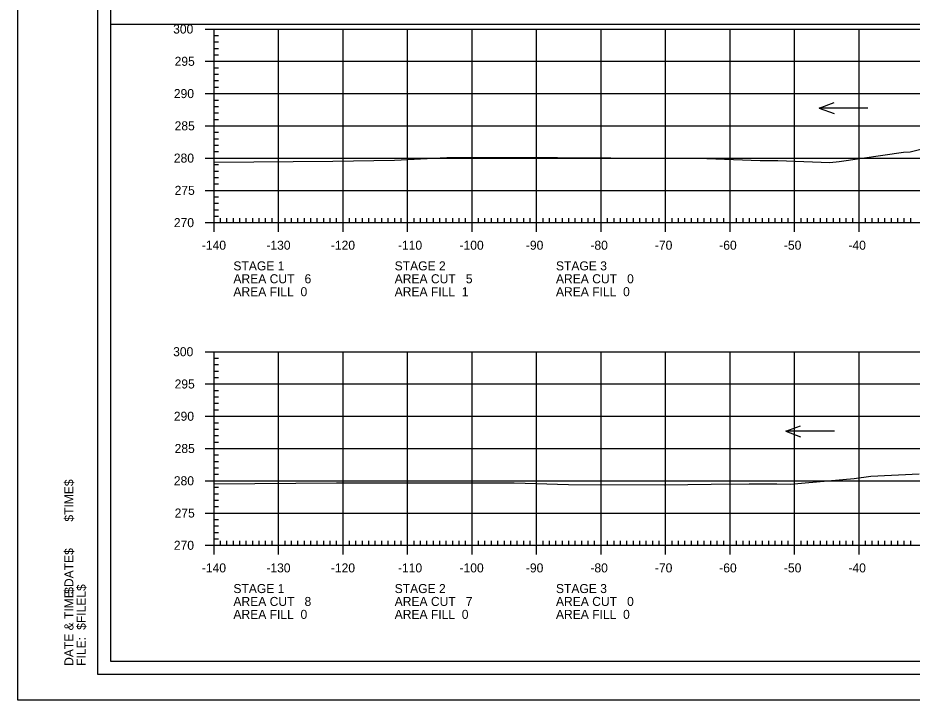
# Model space of a CAD drawing. Extents: x 1368713 to 1370673, y 380279 to 380950.
# Drawn here: x 1370339.2 to 1370477.8, y 380310.4 to 380416.1 of the extents above; entities that cross this region are included whole.
import ezdxf

# ---------------------------------------------------------------- set-up
doc = ezdxf.new("R2010")
doc.units = 0
for name, color, linetype in [('R_Axis', 7, 'Continuous'), ('R_Axis Annot', 7, 'Continuous'), ('R_Border', 7, 'Continuous'), ('R_Border Notes', 7, 'Continuous'), ('R_Exist Surface', 7, 'Continuous'), ('R_Grid', 7, 'Continuous'), ('R_No Plot', 7, 'Continuous'), ('R_Water Annot', 7, 'Continuous')]:
    doc.layers.add(name, color=color, linetype=linetype)

msp = doc.modelspace()

# ---------------------------------------------------------------- linework, layer by layer
at = {"layer": 'R_Axis'}
for p, q in [((1370368.23, 380414.42), (1370371.03, 380414.42)), ((1370369.63, 380384.42), (1370369.63, 380414.42)), ((1370369.63, 380413.42), (1370370.33, 380413.42)), ((1370369.63, 380412.42), (1370370.33, 380412.42)), ((1370369.63, 380411.42), (1370370.33, 380411.42)), ((1370369.63, 380410.42), (1370370.33, 380410.42)), ((1370368.23, 380409.42), (1370371.03, 380409.42)), ((1370369.63, 380408.42), (1370370.33, 380408.42)), ((1370369.63, 380407.42), (1370370.33, 380407.42)), ((1370369.63, 380406.42), (1370370.33, 380406.42)), ((1370369.63, 380405.42), (1370370.33, 380405.42)), ((1370368.23, 380404.42), (1370371.03, 380404.42)), ((1370369.63, 380403.42), (1370370.33, 380403.42)), ((1370369.63, 380402.42), (1370370.33, 380402.42)), ((1370369.63, 380401.42), (1370370.33, 380401.42)), ((1370369.63, 380400.42), (1370370.33, 380400.42)), ((1370368.23, 380399.42), (1370371.03, 380399.42)), ((1370369.63, 380398.42), (1370370.33, 380398.42)), ((1370369.63, 380397.42), (1370370.33, 380397.42)), ((1370369.63, 380396.42), (1370370.33, 380396.42)), ((1370368.23, 380394.42), (1370371.03, 380394.42)), ((1370369.63, 380395.42), (1370370.33, 380395.42)), ((1370369.63, 380393.42), (1370370.33, 380393.42)), ((1370369.63, 380392.42), (1370370.33, 380392.42)), ((1370369.63, 380391.42), (1370370.33, 380391.42)), ((1370369.63, 380390.42), (1370370.33, 380390.42)), ((1370368.23, 380389.42), (1370371.03, 380389.42)), ((1370369.63, 380388.42), (1370370.33, 380388.42)), ((1370369.63, 380387.42), (1370370.33, 380387.42)), ((1370369.63, 380386.42), (1370370.33, 380386.42)), ((1370369.63, 380383.02), (1370369.63, 380385.82)), ((1370369.63, 380385.42), (1370370.33, 380385.42)), ((1370370.63, 380384.42), (1370370.63, 380385.12)), ((1370371.63, 380384.42), (1370371.63, 380385.12)), ((1370372.63, 380384.42), (1370372.63, 380385.12)), ((1370373.63, 380384.42), (1370373.63, 380385.12)), ((1370374.63, 380384.42), (1370374.63, 380385.12)), ((1370375.63, 380384.42), (1370375.63, 380385.12)), ((1370376.63, 380384.42), (1370376.63, 380385.12)), ((1370377.63, 380384.42), (1370377.63, 380385.12)), ((1370378.63, 380384.42), (1370378.63, 380385.12)), ((1370379.63, 380383.02), (1370379.63, 380385.82)), ((1370380.63, 380384.42), (1370380.63, 380385.12)), ((1370381.63, 380384.42), (1370381.63, 380385.12)), ((1370382.63, 380384.42), (1370382.63, 380385.12)), ((1370383.63, 380384.42), (1370383.63, 380385.12)), ((1370384.63, 380384.42), (1370384.63, 380385.12)), ((1370385.63, 380384.42), (1370385.63, 380385.12)), ((1370386.63, 380384.42), (1370386.63, 380385.12)), ((1370387.63, 380384.42), (1370387.63, 380385.12)), ((1370388.63, 380384.42), (1370388.63, 380385.12)), ((1370389.63, 380383.02), (1370389.63, 380385.82)), ((1370390.63, 380384.42), (1370390.63, 380385.12)), ((1370391.63, 380384.42), (1370391.63, 380385.12)), ((1370392.63, 380384.42), (1370392.63, 380385.12)), ((1370393.63, 380384.42), (1370393.63, 380385.12)), ((1370394.63, 380384.42), (1370394.63, 380385.12)), ((1370395.63, 380384.42), (1370395.63, 380385.12)), ((1370396.63, 380384.42), (1370396.63, 380385.12)), ((1370397.63, 380384.42), (1370397.63, 380385.12)), ((1370398.63, 380384.42), (1370398.63, 380385.12)), ((1370399.63, 380383.02), (1370399.63, 380385.82)), ((1370400.63, 380384.42), (1370400.63, 380385.12)), ((1370401.63, 380384.42), (1370401.63, 380385.12)), ((1370402.63, 380384.42), (1370402.63, 380385.12)), ((1370403.63, 380384.42), (1370403.63, 380385.12)), ((1370404.63, 380384.42), (1370404.63, 380385.12)), ((1370405.63, 380384.42), (1370405.63, 380385.12)), ((1370406.63, 380384.42), (1370406.63, 380385.12)), ((1370407.63, 380384.42), (1370407.63, 380385.12)), ((1370408.63, 380384.42), (1370408.63, 380385.12)), ((1370409.63, 380383.02), (1370409.63, 380385.82)), ((1370410.63, 380384.42), (1370410.63, 380385.12)), ((1370411.63, 380384.42), (1370411.63, 380385.12)), ((1370412.63, 380384.42), (1370412.63, 380385.12)), ((1370413.63, 380384.42), (1370413.63, 380385.12)), ((1370414.63, 380384.42), (1370414.63, 380385.12)), ((1370415.63, 380384.42), (1370415.63, 380385.12)), ((1370416.63, 380384.42), (1370416.63, 380385.12)), ((1370417.63, 380384.42), (1370417.63, 380385.12)), ((1370418.63, 380384.42), (1370418.63, 380385.12)), ((1370419.63, 380383.02), (1370419.63, 380385.82)), ((1370420.63, 380384.42), (1370420.63, 380385.12)), ((1370421.63, 380384.42), (1370421.63, 380385.12)), ((1370422.63, 380384.42), (1370422.63, 380385.12)), ((1370423.63, 380384.42), (1370423.63, 380385.12)), ((1370424.63, 380384.42), (1370424.63, 380385.12)), ((1370425.63, 380384.42), (1370425.63, 380385.12)), ((1370426.63, 380384.42), (1370426.63, 380385.12)), ((1370427.63, 380384.42), (1370427.63, 380385.12)), ((1370428.63, 380384.42), (1370428.63, 380385.12)), ((1370429.63, 380383.02), (1370429.63, 380385.82)), ((1370430.63, 380384.42), (1370430.63, 380385.12)), ((1370431.63, 380384.42), (1370431.63, 380385.12)), ((1370432.63, 380384.42), (1370432.63, 380385.12)), ((1370433.63, 380384.42), (1370433.63, 380385.12)), ((1370434.63, 380384.42), (1370434.63, 380385.12)), ((1370435.63, 380384.42), (1370435.63, 380385.12)), ((1370436.63, 380384.42), (1370436.63, 380385.12)), ((1370437.63, 380384.42), (1370437.63, 380385.12)), ((1370438.63, 380384.42), (1370438.63, 380385.12)), ((1370439.63, 380383.02), (1370439.63, 380385.82)), ((1370440.63, 380384.42), (1370440.63, 380385.12)), ((1370441.63, 380384.42), (1370441.63, 380385.12)), ((1370442.63, 380384.42), (1370442.63, 380385.12)), ((1370443.63, 380384.42), (1370443.63, 380385.12)), ((1370444.63, 380384.42), (1370444.63, 380385.12)), ((1370445.63, 380384.42), (1370445.63, 380385.12)), ((1370446.63, 380384.42), (1370446.63, 380385.12)), ((1370447.63, 380384.42), (1370447.63, 380385.12)), ((1370448.63, 380384.42), (1370448.63, 380385.12)), ((1370449.63, 380383.02), (1370449.63, 380385.82)), ((1370450.63, 380384.42), (1370450.63, 380385.12)), ((1370451.63, 380384.42), (1370451.63, 380385.12)), ((1370452.63, 380384.42), (1370452.63, 380385.12)), ((1370453.63, 380384.42), (1370453.63, 380385.12)), ((1370454.63, 380384.42), (1370454.63, 380385.12)), ((1370455.63, 380384.42), (1370455.63, 380385.12)), ((1370456.63, 380384.42), (1370456.63, 380385.12)), ((1370457.63, 380384.42), (1370457.63, 380385.12)), ((1370458.63, 380384.42), (1370458.63, 380385.12)), ((1370459.63, 380383.02), (1370459.63, 380385.82)), ((1370460.63, 380384.42), (1370460.63, 380385.12)), ((1370461.63, 380384.42), (1370461.63, 380385.12)), ((1370462.63, 380384.42), (1370462.63, 380385.12)), ((1370463.63, 380384.42), (1370463.63, 380385.12)), ((1370464.63, 380384.42), (1370464.63, 380385.12)), ((1370465.63, 380384.42), (1370465.63, 380385.12)), ((1370466.63, 380384.42), (1370466.63, 380385.12)), ((1370467.63, 380384.42), (1370467.63, 380385.12)), ((1370468.63, 380384.42), (1370468.63, 380385.12)), ((1370469.63, 380383.02), (1370469.63, 380385.82)), ((1370470.63, 380384.42), (1370470.63, 380385.12)), ((1370471.63, 380384.42), (1370471.63, 380385.12)), ((1370472.63, 380384.42), (1370472.63, 380385.12)), ((1370473.63, 380384.42), (1370473.63, 380385.12)), ((1370474.63, 380384.42), (1370474.63, 380385.12)), ((1370475.63, 380384.42), (1370475.63, 380385.12)), ((1370476.63, 380384.42), (1370476.63, 380385.12)), ((1370477.63, 380384.42), (1370477.63, 380385.12)), ((1370368.23, 380384.42), (1370371.03, 380384.42)), ((1370369.63, 380384.42), (1370649.63, 380384.42)), ((1370368.23, 380364.42), (1370371.03, 380364.42)), ((1370369.63, 380334.42), (1370369.63, 380364.42)), ((1370369.63, 380363.42), (1370370.33, 380363.42)), ((1370369.63, 380362.42), (1370370.33, 380362.42)), ((1370369.63, 380361.42), (1370370.33, 380361.42)), ((1370369.63, 380360.42), (1370370.33, 380360.42)), ((1370368.23, 380359.42), (1370371.03, 380359.42)), ((1370369.63, 380358.42), (1370370.33, 380358.42)), ((1370369.63, 380357.42), (1370370.33, 380357.42)), ((1370369.63, 380356.42), (1370370.33, 380356.42)), ((1370369.63, 380355.42), (1370370.33, 380355.42)), ((1370368.23, 380354.42), (1370371.03, 380354.42)), ((1370369.63, 380353.42), (1370370.33, 380353.42)), ((1370369.63, 380352.42), (1370370.33, 380352.42)), ((1370369.63, 380351.42), (1370370.33, 380351.42)), ((1370369.63, 380350.42), (1370370.33, 380350.42)), ((1370368.23, 380349.42), (1370371.03, 380349.42)), ((1370369.63, 380348.42), (1370370.33, 380348.42)), ((1370369.63, 380347.42), (1370370.33, 380347.42)), ((1370369.63, 380346.42), (1370370.33, 380346.42)), ((1370368.23, 380344.42), (1370371.03, 380344.42)), ((1370369.63, 380345.42), (1370370.33, 380345.42)), ((1370369.63, 380343.42), (1370370.33, 380343.42)), ((1370369.63, 380342.42), (1370370.33, 380342.42)), ((1370369.63, 380341.42), (1370370.33, 380341.42)), ((1370369.63, 380340.42), (1370370.33, 380340.42)), ((1370368.23, 380339.42), (1370371.03, 380339.42)), ((1370369.63, 380338.42), (1370370.33, 380338.42)), ((1370369.63, 380337.42), (1370370.33, 380337.42)), ((1370369.63, 380336.42), (1370370.33, 380336.42)), ((1370369.63, 380333.02), (1370369.63, 380335.82)), ((1370369.63, 380335.42), (1370370.33, 380335.42)), ((1370370.63, 380334.42), (1370370.63, 380335.12)), ((1370371.63, 380334.42), (1370371.63, 380335.12)), ((1370372.63, 380334.42), (1370372.63, 380335.12)), ((1370373.63, 380334.42), (1370373.63, 380335.12)), ((1370374.63, 380334.42), (1370374.63, 380335.12)), ((1370375.63, 380334.42), (1370375.63, 380335.12)), ((1370376.63, 380334.42), (1370376.63, 380335.12)), ((1370377.63, 380334.42), (1370377.63, 380335.12)), ((1370378.63, 380334.42), (1370378.63, 380335.12)), ((1370379.63, 380333.02), (1370379.63, 380335.82)), ((1370380.63, 380334.42), (1370380.63, 380335.12)), ((1370381.63, 380334.42), (1370381.63, 380335.12)), ((1370382.63, 380334.42), (1370382.63, 380335.12)), ((1370383.63, 380334.42), (1370383.63, 380335.12)), ((1370384.63, 380334.42), (1370384.63, 380335.12)), ((1370385.63, 380334.42), (1370385.63, 380335.12)), ((1370386.63, 380334.42), (1370386.63, 380335.12)), ((1370387.63, 380334.42), (1370387.63, 380335.12)), ((1370388.63, 380334.42), (1370388.63, 380335.12)), ((1370389.63, 380333.02), (1370389.63, 380335.82)), ((1370390.63, 380334.42), (1370390.63, 380335.12)), ((1370391.63, 380334.42), (1370391.63, 380335.12)), ((1370392.63, 380334.42), (1370392.63, 380335.12)), ((1370393.63, 380334.42), (1370393.63, 380335.12)), ((1370394.63, 380334.42), (1370394.63, 380335.12)), ((1370395.63, 380334.42), (1370395.63, 380335.12)), ((1370396.63, 380334.42), (1370396.63, 380335.12)), ((1370397.63, 380334.42), (1370397.63, 380335.12)), ((1370398.63, 380334.42), (1370398.63, 380335.12)), ((1370399.63, 380333.02), (1370399.63, 380335.82)), ((1370400.63, 380334.42), (1370400.63, 380335.12)), ((1370401.63, 380334.42), (1370401.63, 380335.12)), ((1370402.63, 380334.42), (1370402.63, 380335.12)), ((1370403.63, 380334.42), (1370403.63, 380335.12)), ((1370404.63, 380334.42), (1370404.63, 380335.12)), ((1370405.63, 380334.42), (1370405.63, 380335.12)), ((1370406.63, 380334.42), (1370406.63, 380335.12)), ((1370407.63, 380334.42), (1370407.63, 380335.12)), ((1370408.63, 380334.42), (1370408.63, 380335.12)), ((1370409.63, 380333.02), (1370409.63, 380335.82)), ((1370410.63, 380334.42), (1370410.63, 380335.12)), ((1370411.63, 380334.42), (1370411.63, 380335.12)), ((1370412.63, 380334.42), (1370412.63, 380335.12)), ((1370413.63, 380334.42), (1370413.63, 380335.12)), ((1370414.63, 380334.42), (1370414.63, 380335.12)), ((1370415.63, 380334.42), (1370415.63, 380335.12)), ((1370416.63, 380334.42), (1370416.63, 380335.12)), ((1370417.63, 380334.42), (1370417.63, 380335.12)), ((1370418.63, 380334.42), (1370418.63, 380335.12)), ((1370419.63, 380333.02), (1370419.63, 380335.82)), ((1370420.63, 380334.42), (1370420.63, 380335.12)), ((1370421.63, 380334.42), (1370421.63, 380335.12)), ((1370422.63, 380334.42), (1370422.63, 380335.12)), ((1370423.63, 380334.42), (1370423.63, 380335.12)), ((1370424.63, 380334.42), (1370424.63, 380335.12)), ((1370425.63, 380334.42), (1370425.63, 380335.12)), ((1370426.63, 380334.42), (1370426.63, 380335.12)), ((1370427.63, 380334.42), (1370427.63, 380335.12)), ((1370428.63, 380334.42), (1370428.63, 380335.12)), ((1370429.63, 380333.02), (1370429.63, 380335.82)), ((1370430.63, 380334.42), (1370430.63, 380335.12)), ((1370431.63, 380334.42), (1370431.63, 380335.12)), ((1370432.63, 380334.42), (1370432.63, 380335.12)), ((1370433.63, 380334.42), (1370433.63, 380335.12)), ((1370434.63, 380334.42), (1370434.63, 380335.12)), ((1370435.63, 380334.42), (1370435.63, 380335.12)), ((1370436.63, 380334.42), (1370436.63, 380335.12)), ((1370437.63, 380334.42), (1370437.63, 380335.12)), ((1370438.63, 380334.42), (1370438.63, 380335.12)), ((1370439.63, 380333.02), (1370439.63, 380335.82)), ((1370440.63, 380334.42), (1370440.63, 380335.12)), ((1370441.63, 380334.42), (1370441.63, 380335.12)), ((1370442.63, 380334.42), (1370442.63, 380335.12)), ((1370443.63, 380334.42), (1370443.63, 380335.12)), ((1370444.63, 380334.42), (1370444.63, 380335.12)), ((1370445.63, 380334.42), (1370445.63, 380335.12)), ((1370446.63, 380334.42), (1370446.63, 380335.12)), ((1370447.63, 380334.42), (1370447.63, 380335.12)), ((1370448.63, 380334.42), (1370448.63, 380335.12)), ((1370449.63, 380333.02), (1370449.63, 380335.82)), ((1370450.63, 380334.42), (1370450.63, 380335.12)), ((1370451.63, 380334.42), (1370451.63, 380335.12)), ((1370452.63, 380334.42), (1370452.63, 380335.12)), ((1370453.63, 380334.42), (1370453.63, 380335.12)), ((1370454.63, 380334.42), (1370454.63, 380335.12)), ((1370455.63, 380334.42), (1370455.63, 380335.12)), ((1370456.63, 380334.42), (1370456.63, 380335.12)), ((1370457.63, 380334.42), (1370457.63, 380335.12)), ((1370458.63, 380334.42), (1370458.63, 380335.12)), ((1370459.63, 380333.02), (1370459.63, 380335.82)), ((1370460.63, 380334.42), (1370460.63, 380335.12)), ((1370461.63, 380334.42), (1370461.63, 380335.12)), ((1370462.63, 380334.42), (1370462.63, 380335.12)), ((1370463.63, 380334.42), (1370463.63, 380335.12)), ((1370464.63, 380334.42), (1370464.63, 380335.12)), ((1370465.63, 380334.42), (1370465.63, 380335.12)), ((1370466.63, 380334.42), (1370466.63, 380335.12)), ((1370467.63, 380334.42), (1370467.63, 380335.12)), ((1370468.63, 380334.42), (1370468.63, 380335.12)), ((1370469.63, 380333.02), (1370469.63, 380335.82)), ((1370470.63, 380334.42), (1370470.63, 380335.12)), ((1370471.63, 380334.42), (1370471.63, 380335.12)), ((1370472.63, 380334.42), (1370472.63, 380335.12)), ((1370473.63, 380334.42), (1370473.63, 380335.12)), ((1370474.63, 380334.42), (1370474.63, 380335.12)), ((1370475.63, 380334.42), (1370475.63, 380335.12)), ((1370476.63, 380334.42), (1370476.63, 380335.12)), ((1370477.63, 380334.42), (1370477.63, 380335.12)), ((1370368.23, 380334.42), (1370371.03, 380334.42)), ((1370369.63, 380334.42), (1370649.63, 380334.42))]:
    msp.add_line(p, q, dxfattribs=at)
at = {"layer": 'R_Border'}
for p, q in [((1370351.63, 380314.42), (1370351.63, 380519.88)), ((1370351.63, 380314.42), (1370351.63, 380314.42)), ((1370667.81, 380314.42), (1370351.63, 380314.42))]:
    msp.add_line(p, q, dxfattribs=at)
at = {"layer": 'R_Exist Surface'}
for points in [[(1370369.63, 380393.77), (1370388.05, 380393.92), (1370397.58, 380394.09), (1370405.74, 380394.51), (1370422.88, 380394.49), (1370431.13, 380394.45), (1370446.02, 380394.36), (1370454.29, 380394.06), (1370457.02, 380394.07), (1370465.11, 380393.76), (1370466.51, 380393.88), (1370476.51, 380395.33), (1370477.53, 380395.38), (1370493.39, 380399.44)], [(1370369.63, 380343.95), (1370388.62, 380344.11), (1370398.17, 380344.11), (1370416.15, 380344.1), (1370424.55, 380343.86), (1370439.46, 380343.77), (1370446.69, 380343.87), (1370452.57, 380343.96), (1370456.85, 380343.97), (1370458.92, 380343.89), (1370468.84, 380344.77), (1370471.43, 380345.15), (1370478.91, 380345.51)]]:
    msp.add_lwpolyline(points, dxfattribs=at)
at = {"layer": 'R_Grid'}
for p, q in [((1370369.63, 380414.42), (1370649.63, 380414.42)), ((1370369.63, 380384.42), (1370369.63, 380414.42)), ((1370379.63, 380384.42), (1370379.63, 380414.42)), ((1370389.63, 380384.42), (1370389.63, 380414.42)), ((1370399.63, 380384.42), (1370399.63, 380414.42)), ((1370409.63, 380384.42), (1370409.63, 380414.42)), ((1370419.63, 380384.42), (1370419.63, 380414.42)), ((1370429.63, 380384.42), (1370429.63, 380414.42)), ((1370439.63, 380384.42), (1370439.63, 380414.42)), ((1370449.63, 380384.42), (1370449.63, 380414.42)), ((1370459.63, 380384.42), (1370459.63, 380414.42)), ((1370469.63, 380384.42), (1370469.63, 380414.42)), ((1370369.63, 380409.42), (1370649.63, 380409.42)), ((1370369.63, 380404.42), (1370649.63, 380404.42)), ((1370369.63, 380399.42), (1370649.63, 380399.42)), ((1370369.63, 380394.42), (1370649.63, 380394.42)), ((1370369.63, 380389.42), (1370649.63, 380389.42)), ((1370369.63, 380384.42), (1370649.63, 380384.42)), ((1370369.63, 380364.42), (1370649.63, 380364.42)), ((1370369.63, 380334.42), (1370369.63, 380364.42)), ((1370379.63, 380334.42), (1370379.63, 380364.42)), ((1370389.63, 380334.42), (1370389.63, 380364.42)), ((1370399.63, 380334.42), (1370399.63, 380364.42)), ((1370409.63, 380334.42), (1370409.63, 380364.42)), ((1370419.63, 380334.42), (1370419.63, 380364.42)), ((1370429.63, 380334.42), (1370429.63, 380364.42)), ((1370439.63, 380334.42), (1370439.63, 380364.42)), ((1370449.63, 380334.42), (1370449.63, 380364.42)), ((1370459.63, 380334.42), (1370459.63, 380364.42)), ((1370469.63, 380334.42), (1370469.63, 380364.42)), ((1370369.63, 380359.42), (1370649.63, 380359.42)), ((1370369.63, 380354.42), (1370649.63, 380354.42)), ((1370369.63, 380349.42), (1370649.63, 380349.42)), ((1370369.63, 380344.42), (1370649.63, 380344.42)), ((1370369.63, 380339.42), (1370649.63, 380339.42)), ((1370369.63, 380334.42), (1370649.63, 380334.42))]:
    msp.add_line(p, q, dxfattribs=at)
at = {"layer": 'R_No Plot'}
for points in [[(1370339.22, 380523.77), (1370672.56, 380523.77), (1370672.56, 380310.43), (1370339.22, 380310.43)], [(1370353.63, 380517.88), (1370603.17, 380517.88), (1370603.17, 380508), (1370620.71, 380508), (1370644.81, 380508), (1370644.81, 380485.66), (1370665.81, 380485.66), (1370665.81, 380316.42), (1370353.63, 380316.42)], [(1370353.63, 380415.15), (1370665.81, 380415.15), (1370665.81, 380316.42), (1370353.63, 380316.42)]]:
    msp.add_lwpolyline(points, close=True, dxfattribs=at)
at = {"layer": 'R_Water Annot'}
for p, q in [((1370463.43, 380402.17), (1370465.74, 380403.01)), ((1370470.97, 380402.17), (1370463.43, 380402.17)), ((1370463.43, 380402.17), (1370465.74, 380401.33)), ((1370458.25, 380352.09), (1370460.56, 380352.93)), ((1370465.79, 380352.09), (1370458.25, 380352.09)), ((1370458.25, 380352.09), (1370460.56, 380351.25))]:
    msp.add_line(p, q, dxfattribs=at)

# ---------------------------------------------------------------- texts
at = {"layer": 'R_Axis Annot'}
for s, p in [('300', (1370363.29, 380413.72)), ('295', (1370363.52, 380408.72)), ('290', (1370363.4, 380403.72)), ('285', (1370363.52, 380398.72)), ('280', (1370363.4, 380393.72)), ('275', (1370363.52, 380388.72)), ('270', (1370363.4, 380383.72)), ('-140', (1370367.74, 380380.22)), ('-130', (1370377.74, 380380.22)), ('-120', (1370387.74, 380380.22)), ('-110', (1370398.14, 380380.22)), ('-100', (1370407.68, 380380.22)), ('-90', (1370417.97, 380380.22)), ('-80', (1370427.97, 380380.22)), ('-70', (1370437.97, 380380.22)), ('-60', (1370447.94, 380380.22)), ('-50', (1370457.97, 380380.22)), ('-40', (1370467.97, 380380.22)), ('STAGE 1', (1370372.63, 380377.02)), ('STAGE 2', (1370397.63, 380377.02)), ('STAGE 3', (1370422.63, 380377.02)), ('AREA CUT   6', (1370372.63, 380375.02)), ('AREA CUT   5', (1370397.63, 380375.02)), ('AREA CUT   0', (1370422.63, 380375.02)), ('AREA FILL  0', (1370372.63, 380373.02)), ('AREA FILL  1', (1370397.63, 380373.02)), ('AREA FILL  0', (1370422.63, 380373.02)), ('300', (1370363.29, 380363.72)), ('295', (1370363.52, 380358.72)), ('290', (1370363.4, 380353.72)), ('285', (1370363.52, 380348.72)), ('280', (1370363.4, 380343.72)), ('275', (1370363.52, 380338.72)), ('270', (1370363.4, 380333.72)), ('-140', (1370367.74, 380330.22)), ('-130', (1370377.74, 380330.22)), ('-120', (1370387.74, 380330.22)), ('-110', (1370398.14, 380330.22)), ('-100', (1370407.68, 380330.22)), ('-90', (1370417.97, 380330.22)), ('-80', (1370427.97, 380330.22)), ('-70', (1370437.97, 380330.22)), ('-60', (1370447.94, 380330.22)), ('-50', (1370457.97, 380330.22)), ('-40', (1370467.97, 380330.22)), ('STAGE 1', (1370372.63, 380327.02)), ('STAGE 2', (1370397.63, 380327.02)), ('STAGE 3', (1370422.63, 380327.02)), ('AREA CUT   8', (1370372.63, 380325.02)), ('AREA CUT   7', (1370397.63, 380325.02)), ('AREA CUT   0', (1370422.63, 380325.02)), ('AREA FILL  0', (1370372.63, 380323.02)), ('AREA FILL  0', (1370397.63, 380323.02)), ('AREA FILL  0', (1370422.63, 380323.02))]:
    msp.add_text(s, height=1.4, dxfattribs=at).set_placement(p)
at = {"layer": 'R_Border Notes'}
for s, height, p in [('$TIME$', 1.397, (1370347.83, 380338.09)), ('$DATE$', 1.397, (1370347.83, 380326.91)), ('DATE & TIME:', 1.3968, (1370347.83, 380315.74)), ('$FILEL$', 1.397, (1370349.75, 380321.32)), ('FILE: ', 1.397, (1370349.75, 380315.74))]:
    msp.add_text(s, height=height, rotation=90, dxfattribs=at).set_placement(p)

doc.saveas('drawing.dxf')
